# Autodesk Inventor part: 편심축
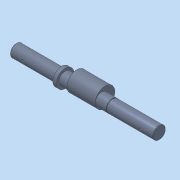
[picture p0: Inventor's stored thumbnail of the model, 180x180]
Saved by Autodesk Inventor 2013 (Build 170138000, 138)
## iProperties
Manager: 한국ATC센터
Company: 한국ATC센터
Created: 2014-10
Part Number: 편심축
Document SubType Name: Modeling
Designer: 한국ATC센터
Density: 7.86 g/cm^3
Material: 강, 연강
Mass: 1420.77 g
Surface Area: 286.546 cm^2
Volume: 180.76 cm^3
Author: KYOUNG IL JANG
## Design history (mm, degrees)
sketch "스케치1"
  geometry: L1 (-142, 0)-(142, 0); L2 (-142, 0)-(-142, 12.5); L3 (-142, 12.5)-(-52, 12.5); L4 (-52, 12.5)-(-52, 17.5); L5 (-52, 17.5)-(-45, 17.5); L6 (-45, 17.5)-(-45, 12.5); L7 (-45, 12.5)-(48.65, 12.5); L8 (48.65, 12.5)-(48.65, 11.95); L9 (48.65, 11.95)-(50, 11.95); L10 (50, 11.95)-(50, 12.5); L11 (50, 12.5)-(142, 12.5); L12 (142, 12.5)-(142, 0); L13 (109, 12.5)-(109, 9.1); L14 (109, 9.1)-(134, 9.1); L15 (134, 9.1)-(134, 12.5); L16 (117, -12.5)-(119.5, -12.5); L17 (119.5, -12.5)-(117, -10); L18 (117, -10)-(117, -12.5); L19 (-109, 12.5)-(-109, 9.1); L20 (-109, 9.1)-(-134, 9.1); L21 (-134, 9.1)-(-134, 12.5); L22 (-117, -12.5)-(-117, -10); L23 (-117, -10)-(-114.5, -12.5); L24 (-114.5, -12.5)-(-117, -12.5); 2 further points
  constraints: 48 end point, 11 parallel, 8 perpendicular, 5 collinear, 4 point on line, 1 coincident, 1 horizontal, 1 midpoint, 1 vertical
  dimensions: "d0" = 284 distance of L1.start L1.end (derived); "d1" = 25 diameter of L3 L1; "d2" = 35 diameter of L5 L1; "d3" = 90 distance of L2.end L3.end; "d4" = 187 distance between parallel lines of L12 L6; "d6" = 1.35 distance of L8.end L9.end; "d7" = 23.9 diameter of L9 L1; "d8" = 3.4 distance between parallel lines of L14 L11; "d9" = 8 distance between parallel lines of L15 L12; "d10" = 25 distance of L13.end L14.end; "d11" = 25 diameter of L16 L1 (= d1); "d12" = 25 distance from line of L12 L16.start; "d13" = 45 deg angle of L17 L18; "d14" = 5 diameter of L16.end L18; "d27" = 92 distance between parallel lines of L10 L12; "d32" = 7 distance of L4.end L5.end; "d33" = 8 distance between parallel lines of L2 L21; "d34" = 25 distance between parallel lines of L21 L19; "d35" = 3.4 distance between parallel lines of L3 L20; "d36" = 25 distance from line of L22.start L2; "d37" = 5 diameter of L23.end L22
revolve "회전1" stored, may be unused: angle "d15" = 90 deg
revolve "회전2" stored, may be unused: angle "d16" = 90 deg
revolve "회전3" stored, may be unused: angle "d38" = 90 deg
extrude "돌출1" cut sketch "스케치1" stored distance "d17" = 8; taper "d18" = 0 deg
fillet "모깎기1" dims "d19" = 4
node "작업 평면1"
sketch "스케치2"
  geometry: L1 (12.99, -6.5)-(8.66, -14); L2 (-12.99, -6.5)-(-8.66, -14); C1 r 12.5 at (0, 0) reference; C2 r 19.5 at (0, 7); A1 r 15 centre (0, 1) between (12.99, -6.5) and (-12.99, -6.5); A2 r 10 centre (0, -9) between (-8.66, -14) and (8.66, -14); 1 further point
  constraints: 5 tangent, 4 end point, 4 point on circle, 3 centre point, 3 vertical alignment
  dimensions: "d21" = 7 distance of point (0, 0) C2.centre; "d30" = 39 diameter of C2 (derived); "d39" = 10 distance of A2.centre A1.centre; "d40" = 30 diameter of A1; "d41" = 20 diameter of A2; "d42" = 1 distance of point (0, 0) A1.centre
extrude "돌출2" join sketch "스케치2" distance "d22" = 56; taper "d23" = 0 deg
chamfer "모따기1" distance "d24" = 1; stored, may be unused: second distance "d25" = 2, angle "d26" = 45 deg
node "솔리드1"
other parameters: "d20" = 16
